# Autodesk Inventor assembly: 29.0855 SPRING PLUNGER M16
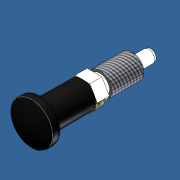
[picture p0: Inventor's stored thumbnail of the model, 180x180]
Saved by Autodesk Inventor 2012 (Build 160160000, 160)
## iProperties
Created: 2016-09
Part Number: 29.0855 SPRING PLUNGER M16
Document SubType Name: Assembly
Designer: Admin
Author: Admin
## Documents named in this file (3)
- C:\Andys Backup Data\ANDY'S INVENTOR\INVENTOR LIBRARIES\PARTS LIBRARY\INDEXING POSITIONING AND FIXTURING\29.0855 SPRING PLUNGER M16.iam
- C:\Andys Backup Data\ANDY'S INVENTOR\INVENTOR LIBRARIES\PARTS LIBRARY\INDEXING POSITIONING AND FIXTURING\SUBCOMPONENTS\29.0855 SPRING PLUNGER THREADED BODY.ipt
- C:\Andys Backup Data\ANDY'S INVENTOR\INVENTOR LIBRARIES\PARTS LIBRARY\INDEXING POSITIONING AND FIXTURING\SUBCOMPONENTS\29.0855 SPRING PLUNGER 8MM PIN.ipt
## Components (2 placed, 2 different names)
1. 29.0855 SPRING PLUNGER THREADED BODY:1 — Insert:1
2. 29.0855 SPRING PLUNGER 8MM PIN:1 — Insert:1
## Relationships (1: Insert 1)
- Insert:1: 29.0855 SPRING PLUNGER THREADED BODY:1 ↔ 29.0855 SPRING PLUNGER 8MM PIN:1
